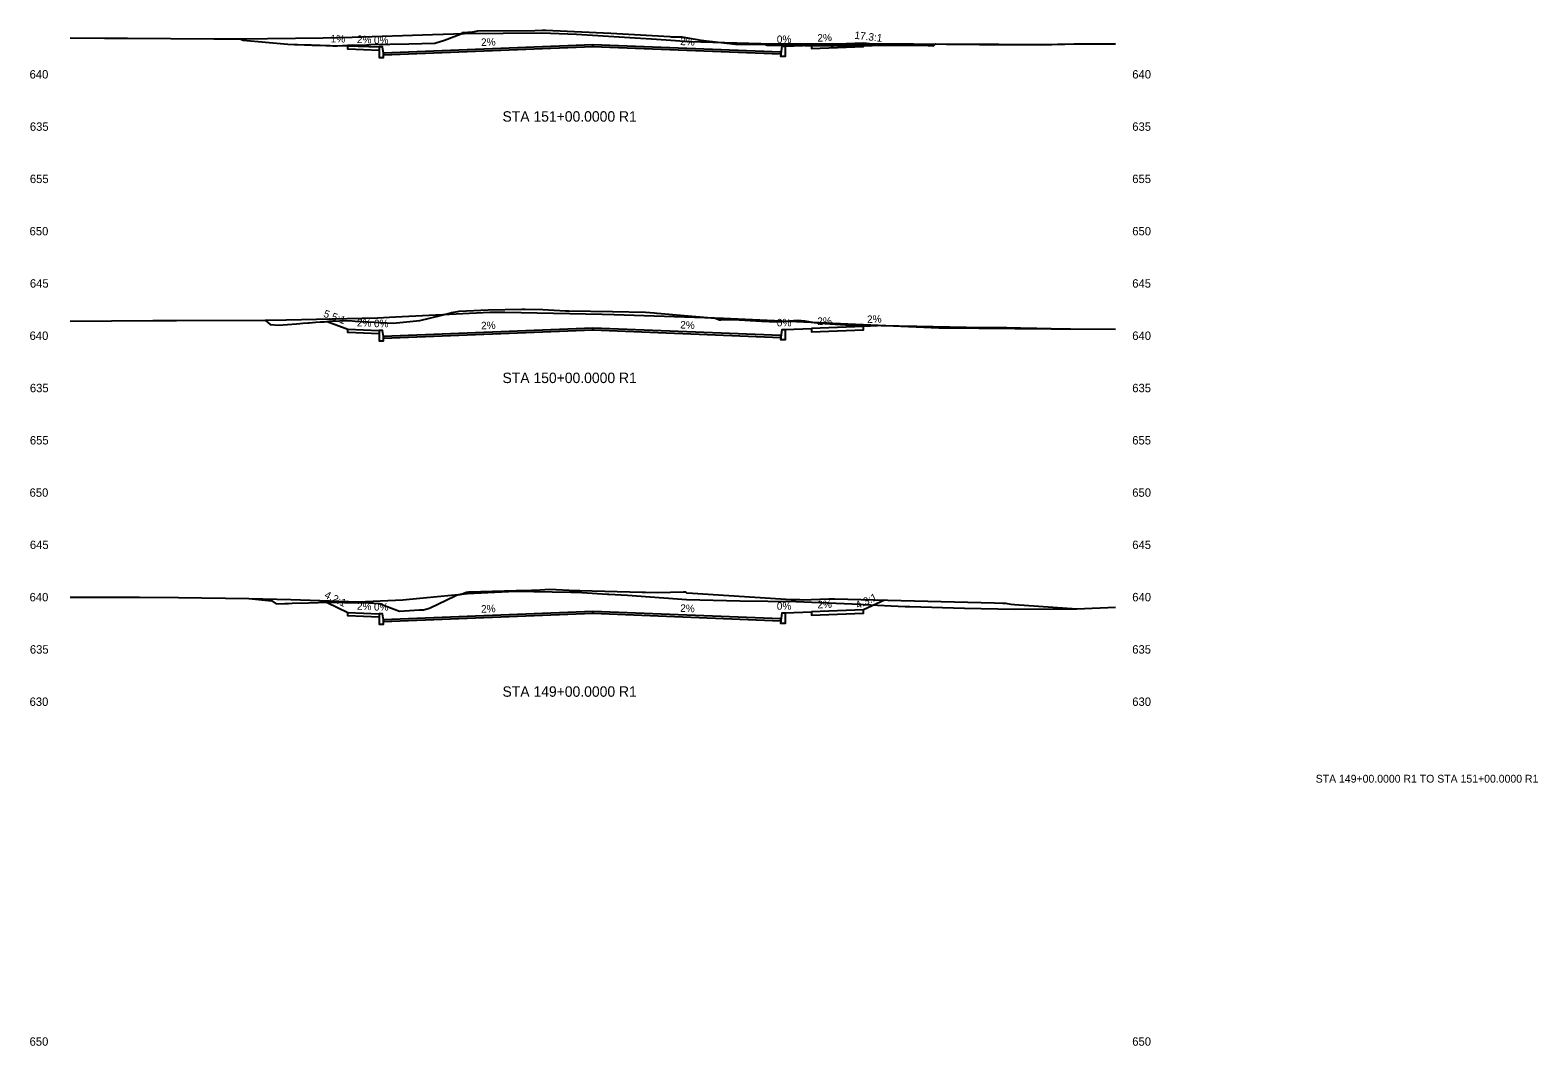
# Model space of a CAD drawing. Extents: x 12 to 301, y 16 to 1707.
# Drawn here: x 12.4 to 300.8, y 1315.6 to 1509.8 of the extents above; entities that cross this region are included whole.
import ezdxf

# ---------------------------------------------------------------- set-up
doc = ezdxf.new("R2010")
doc.units = 0
for name, color, linetype in [('BORD_text_large_2', 7, 'Continuous'), ('Default', 7, 'Continuous'), ('Draft_XS_Point_Label_Indicator', 7, 'Continuous'), ('Draft_XS_Text', 7, 'Continuous'), ('Grade_Veg_Grass', 7, 'Continuous'), ('P_XS_Sections', 7, 'Continuous'), ('Road_Curb', 7, 'Continuous'), ('Road_Pave_Asphalt', 7, 'Continuous'), ('Road_Sidewalk', 7, 'Continuous'), ('Terrain_Exterior', 7, 'Continuous')]:
    doc.layers.add(name, color=color, linetype=linetype)

msp = doc.modelspace()

# ---------------------------------------------------------------- linework, layer by layer
at = {"layer": 'Default'}
for points in [[(20, 1508.36), (26.58, 1508.35), (30.99, 1508.33), (47.51, 1508.2), (52.47, 1508.19), (53.12, 1507.91), (61.69, 1507.17), (62.92, 1507.13), (63.51, 1507.11), (64.83, 1507.06), (65.88, 1507.03), (66.1, 1507.02), (66.32, 1507.01), (67.86, 1506.96), (68.91, 1506.92), (68.98, 1506.92), (69.06, 1506.92), (69.76, 1506.9), (70.29, 1506.88), (70.32, 1506.88), (70.35, 1506.87), (70.76, 1506.86), (70.76, 1506.86), (71.08, 1506.85), (71.1, 1506.85), (71.1, 1506.85), (71.1, 1506.85), (74.09, 1507.07), (75.94, 1506.97), (77.52, 1507.12), (84.85, 1507.21), (89.82, 1507.36), (91.63, 1507.92), (94.8, 1509.15), (95.17, 1509.38), (97.09, 1509.56), (98.03, 1509.72), (108.95, 1509.81), (110.3, 1509.85), (110.54, 1509.85), (110.95, 1509.84), (110.97, 1509.83), (123.47, 1509.25), (131.36, 1508.81), (134.76, 1508.61), (135, 1508.59), (135.63, 1508.59), (136.13, 1508.57), (137.07, 1508.58), (140.67, 1507.92), (147.32, 1507.2), (153.04, 1507.09), (153.21, 1507.02), (153.37, 1506.96), (157.58, 1507.01), (160.52, 1506.94), (165.62, 1506.88), (165.97, 1506.83), (180.94, 1506.98), (182.19, 1507.01), (183.17, 1506.95), (185.21, 1506.86), (185.38, 1507.07), (185.55, 1507.25), (196.01, 1507.19), (197.72, 1507.2), (205.81, 1507.07), (206.09, 1507.08), (207.84, 1507.13), (208.95, 1507.16), (210.34, 1507.19), (212.03, 1507.23), (214.93, 1507.23), (220, 1507.27)], [(20, 1454.16), (35.86, 1454.3), (40.4, 1454.32), (57.35, 1454.41), (58.28, 1453.58), (59.9, 1453.44), (63.34, 1453.69), (63.94, 1453.74), (64.55, 1453.79), (65.56, 1453.86), (65.65, 1453.87), (65.74, 1453.88), (67.04, 1453.97), (67.93, 1454.04), (67.96, 1454.04), (68, 1454.05), (68.63, 1454.09), (69.1, 1454.13), (69.12, 1454.13), (69.14, 1454.13), (69.51, 1454.16), (69.58, 1454.16), (69.63, 1454.17), (69.64, 1454.17), (73.44, 1454.29), (74.56, 1454.21), (80.58, 1453.87), (81.8, 1453.82), (86.9, 1454.3), (90.86, 1455.28), (92.83, 1455.8), (92.96, 1455.86), (94.11, 1456.04), (94.44, 1456.11), (99.97, 1456.37), (106.41, 1456.48), (106.78, 1456.47), (107.1, 1456.47), (110.44, 1456.43), (114.77, 1456.18), (115.05, 1456.17), (115.4, 1456.17), (123.81, 1456.02), (130.1, 1455.92), (131.78, 1455.76), (132.23, 1455.71), (132.28, 1455.72), (132.3, 1455.71), (143.42, 1454.74), (144.24, 1454.46), (144.5, 1454.46), (145.95, 1454.49), (146.94, 1454.52), (152.26, 1454.17), (155.22, 1454.07), (155.98, 1454.14), (159.22, 1454.35), (160.5, 1454.24), (162.35, 1453.92), (163.47, 1453.8), (168.39, 1453.48), (182, 1453.22), (191.45, 1453.05), (199.23, 1452.98), (204.44, 1452.82), (204.98, 1452.82), (205.94, 1452.8), (206.18, 1452.8), (206.19, 1452.8), (207.72, 1452.76), (207.76, 1452.75), (207.82, 1452.75), (211.42, 1452.72), (220, 1452.64)], [(20, 1401.41), (33.28, 1401.39), (40.74, 1401.34), (54.21, 1401.14), (58.58, 1400.69), (59.47, 1400.14), (61.08, 1400.19), (61.81, 1400.21), (62.52, 1400.24), (65.64, 1400.34), (67.47, 1400.4), (67.83, 1400.41), (67.83, 1400.41), (77.11, 1400.34), (79.17, 1400.19), (83.06, 1398.71), (86.85, 1398.98), (87.6, 1398.95), (88.8, 1399.28), (93.69, 1401.65), (93.94, 1401.79), (94.56, 1401.9), (94.68, 1401.96), (95.01, 1402.02), (95.85, 1402.34), (96.31, 1402.41), (105.37, 1402.64), (108.27, 1402.74), (108.43, 1402.74), (108.96, 1402.74), (111.78, 1402.91), (116.69, 1402.7), (116.78, 1402.7), (116.79, 1402.7), (117.35, 1402.7), (117.54, 1402.69), (129.47, 1402.38), (129.5, 1402.37), (130.1, 1402.33), (132.38, 1402.3), (137.39, 1402.43), (137.77, 1402.42), (137.91, 1402.25), (137.92, 1402.24), (139.09, 1402.17), (157.97, 1400.98), (158.8, 1400.93), (159.47, 1400.93), (159.62, 1400.92), (160.08, 1400.89), (165.17, 1401.08), (166.27, 1401.05), (179.04, 1400.77), (196.85, 1400.31), (198.43, 1400.28), (198.44, 1400.28), (198.44, 1400.28), (198.45, 1400.28), (198.47, 1400.27), (198.48, 1400.27), (198.49, 1400.27), (198.5, 1400.27), (198.5, 1400.27), (198.51, 1400.27), (198.53, 1400.27), (198.56, 1400.26), (198.6, 1400.26), (198.65, 1400.25), (198.68, 1400.25), (198.73, 1400.24), (198.82, 1400.23), (198.95, 1400.22), (199.26, 1400.18), (200.02, 1400.08), (200.7, 1399.97), (212.6, 1399.18), (220, 1399.5)]]:
    msp.add_lwpolyline(points, dxfattribs=at)
at = {"layer": 'Grade_Veg_Grass'}
for points in [[(69.17, 1506.92), (69.17, 1506.92), (73.17, 1506.87)], [(156.83, 1506.79), (161.83, 1506.99)], [(175.83, 1506.93), (171.83, 1507.39), (171.83, 1507.39)], [(69.17, 1454.13), (69.17, 1454.13), (73.17, 1452.67)], [(156.83, 1452.59), (161.83, 1452.79)], [(175.83, 1453.34), (171.83, 1453.19), (171.83, 1453.19)], [(69.17, 1400.4), (69.17, 1400.4), (73.17, 1398.47)], [(175.83, 1400.84), (175.83, 1400.84), (171.83, 1398.99)], [(156.83, 1398.39), (161.83, 1398.59)]]:
    msp.add_lwpolyline(points, dxfattribs=at)
at = {"layer": 'Road_Curb'}
for points in [[(79.17, 1506.63), (79.17, 1504.63), (80, 1504.63), (80, 1505.47), (79.77, 1506.63), (79.17, 1506.63)], [(156.83, 1506.79), (156.83, 1504.79), (156, 1504.79), (156.23, 1506.79), (156.83, 1506.79)], [(79.17, 1452.43), (79.17, 1450.43), (80, 1450.43), (80, 1451.27), (79.77, 1452.43), (79.17, 1452.43)], [(156.83, 1452.59), (156.83, 1450.59), (156, 1450.59), (156.23, 1452.59), (156.83, 1452.59)], [(79.17, 1398.23), (79.17, 1396.23), (80, 1396.23), (80, 1397.07), (79.77, 1398.23), (79.17, 1398.23)], [(156.83, 1398.39), (156.83, 1396.39), (156, 1396.39), (156.23, 1398.39), (156.83, 1398.39)]]:
    msp.add_lwpolyline(points, dxfattribs=at)
at = {"layer": 'Road_Pave_Asphalt'}
for points in [[(120, 1507.07), (80, 1505.47), (80, 1505.47), (80, 1505.13), (120, 1506.73), (120, 1506.73), (120, 1507.07), (120, 1507.07), (120, 1507.07)], [(120, 1507.07), (120, 1507.07), (120, 1507.07), (120, 1506.73), (120, 1506.73), (156, 1505.29), (156, 1505.63), (156, 1505.63), (120, 1507.07)], [(120, 1452.87), (80, 1451.27), (80, 1451.27), (80, 1450.93), (120, 1452.53), (120, 1452.53), (120, 1452.87), (120, 1452.87), (120, 1452.87)], [(120, 1452.87), (120, 1452.87), (120, 1452.87), (120, 1452.53), (120, 1452.53), (156, 1451.09), (156, 1451.43), (156, 1451.43), (120, 1452.87)], [(120, 1398.67), (80, 1397.07), (80, 1397.07), (80, 1396.73), (120, 1398.33), (120, 1398.33), (120, 1398.67), (120, 1398.67), (120, 1398.67)], [(120, 1398.67), (120, 1398.67), (120, 1398.67), (120, 1398.33), (120, 1398.33), (156, 1396.89), (156, 1397.23), (156, 1397.23), (120, 1398.67)]]:
    msp.add_lwpolyline(points, dxfattribs=at)
at = {"layer": 'Road_Sidewalk'}
for points in [[(79.17, 1506.63), (79.17, 1505.97), (73.17, 1506.21), (73.17, 1506.87), (79.17, 1506.63)], [(161.83, 1506.99), (161.83, 1506.33), (171.83, 1506.73), (171.83, 1507.39), (161.83, 1506.99)], [(79.17, 1452.43), (79.17, 1451.77), (73.17, 1452.01), (73.17, 1452.67), (79.17, 1452.43)], [(161.83, 1452.79), (161.83, 1452.13), (171.83, 1452.53), (171.83, 1453.19), (161.83, 1452.79)], [(161.83, 1398.59), (161.83, 1397.93), (171.83, 1398.33), (171.83, 1398.99), (161.83, 1398.59)], [(79.17, 1398.23), (79.17, 1397.57), (73.17, 1397.81), (73.17, 1398.47), (79.17, 1398.23)]]:
    msp.add_lwpolyline(points, dxfattribs=at)
at = {"layer": 'Terrain_Exterior'}
for points in [[(20, 1508.36), (26.58, 1508.35), (30.99, 1508.33), (47.51, 1508.2), (52.47, 1508.19), (68.44, 1508.4), (73.96, 1508.52), (89.37, 1509.01), (95.44, 1509.24), (110.29, 1509.32), (116.92, 1509.1), (129.16, 1508.33), (131.22, 1508.2), (134.05, 1508), (135.86, 1507.87), (138.4, 1507.68), (152.15, 1507.27), (159.89, 1507.24), (173.08, 1507.24), (181.37, 1507.23), (194.01, 1507.11), (202.85, 1507.09), (214.93, 1507.21), (220, 1507.26)], [(20, 1454.16), (35.86, 1454.3), (40.4, 1454.32), (57.35, 1454.41), (61.32, 1454.43), (78.83, 1454.85), (82.25, 1455.03), (100.31, 1455.88), (103.18, 1455.91), (121.79, 1455.54), (124.11, 1455.45), (143.28, 1454.82), (145.04, 1454.77), (146.34, 1454.71), (161.76, 1454), (164.76, 1453.86), (165.96, 1453.8), (186.24, 1452.91), (186.89, 1452.89), (207.72, 1452.75), (207.82, 1452.75), (211.42, 1452.72), (220, 1452.64)], [(20, 1401.41), (33.28, 1401.39), (40.74, 1401.34), (54.21, 1401.14), (62.22, 1400.95), (75.14, 1400.48), (83.7, 1400.87), (86.95, 1401.2), (94.95, 1402), (96.07, 1402.11), (105.19, 1402.52), (115.81, 1402.38), (116.99, 1402.36), (122.83, 1402), (123.1, 1401.98), (126.67, 1401.76), (137.92, 1400.96), (148.15, 1400.68), (158.85, 1400.54), (169.63, 1400.1), (171.3, 1400.03), (171.83, 1400), (179.78, 1399.62), (180.64, 1399.6), (191.11, 1399.3), (200.7, 1399.07), (212.6, 1399.18), (220, 1399.5)]]:
    msp.add_lwpolyline(points, dxfattribs=at)

# ---------------------------------------------------------------- texts
at = {"layer": 'BORD_text_large_2'}
msp.add_text('STA 149+00.0000 R1 TO STA 151+00.0000 R1', height=1.5, dxfattribs=at).set_placement((258.32, 1365.92))
at = {"layer": 'Draft_XS_Point_Label_Indicator'}
for p in [(69.16, 1506.9), (73.16, 1506.86), (79.16, 1506.62), (79.76, 1506.62), (119.99, 1507.06), (119.99, 1507.06), (156.22, 1506.78), (156.82, 1506.78), (161.82, 1506.98), (171.82, 1507.38), (175.82, 1506.92), (79.99, 1505.46), (155.99, 1505.62), (69.16, 1454.12), (73.16, 1452.66), (79.16, 1452.42), (79.76, 1452.42), (79.99, 1451.26), (119.99, 1452.86), (119.99, 1452.86), (155.99, 1451.42), (156.22, 1452.58), (156.82, 1452.58), (161.82, 1452.78), (171.82, 1453.18), (175.82, 1453.33), (69.16, 1400.39), (171.82, 1398.98), (175.82, 1400.83), (73.16, 1398.46), (79.16, 1398.22), (79.76, 1398.22), (79.99, 1397.06), (119.99, 1398.66), (119.99, 1398.66), (155.99, 1397.22), (156.22, 1398.38), (156.82, 1398.38), (161.82, 1398.58)]:
    msp.add_text('X', height=0.024, dxfattribs=at).set_placement(p)
at = {"layer": 'Draft_XS_Text'}
for s, rotation, p in [('1%', 359.4187, (69.86, 1507.51)), ('1%', 359.4187, (69.86, 1507.51)), ('1%', 359.4187, (69.86, 1507.51)), ('2%', 357.7094, (74.88, 1507.41)), ('2%', 357.7094, (74.88, 1507.41)), ('2%', 357.7094, (74.88, 1507.41)), ('0%', 360, (78.15, 1507.23)), ('0%', 360, (78.15, 1507.23)), ('0%', 360, (78.15, 1507.23)), ('0%', 0, (155.22, 1507.39)), ('0%', 0, (155.22, 1507.39)), ('0%', 0, (155.22, 1507.39)), ('2%', 2.2906, (163, 1507.64)), ('2%', 2.2906, (163, 1507.64)), ('2%', 2.2906, (163, 1507.64)), ('17.3:1', 353.4149, (170.01, 1508.21)), ('17.3:1', 353.4149, (170.01, 1508.21)), ('17.3:1', 353.4149, (170.01, 1508.21)), ('2%', 2.2906, (98.66, 1506.81)), ('2%', 2.2906, (98.66, 1506.81)), ('2%', 2.2906, (98.66, 1506.81)), ('2%', 357.7094, (136.71, 1507)), ('2%', 357.7094, (136.71, 1507)), ('2%', 357.7094, (136.71, 1507)), ('5.5:1', 339.962, (68.37, 1455.06)), ('5.5:1', 339.962, (68.37, 1455.06)), ('5.5:1', 339.962, (68.37, 1455.06)), ('2%', 357.7094, (74.88, 1453.21)), ('2%', 357.7094, (74.88, 1453.21)), ('2%', 357.7094, (74.88, 1453.21)), ('0%', 0, (78.15, 1453.03)), ('0%', 0, (78.15, 1453.03)), ('0%', 0, (78.15, 1453.03)), ('2%', 2.2906, (98.66, 1452.61)), ('2%', 2.2906, (98.66, 1452.61)), ('2%', 2.2906, (98.66, 1452.61)), ('2%', 357.7094, (136.71, 1452.8)), ('2%', 357.7094, (136.71, 1452.8)), ('2%', 357.7094, (136.71, 1452.8)), ('0%', 0, (155.22, 1453.19)), ('0%', 0, (155.22, 1453.19)), ('0%', 0, (155.22, 1453.19)), ('2%', 2.2906, (163, 1453.44)), ('2%', 2.2906, (163, 1453.44)), ('2%', 2.2906, (163, 1453.44)), ('2%', 2.0751, (172.5, 1453.82)), ('2%', 2.0751, (172.5, 1453.82)), ('2%', 2.0751, (172.5, 1453.82)), ('4.2:1', 334.3023, (68.54, 1401.36)), ('4.2:1', 334.3023, (68.54, 1401.36)), ('4.2:1', 334.3023, (68.54, 1401.36)), ('4.3:1', 24.7976, (170.68, 1399.12)), ('4.3:1', 24.7976, (170.68, 1399.12)), ('4.3:1', 24.7976, (170.68, 1399.12)), ('2%', 357.7094, (74.88, 1399.01)), ('2%', 357.7094, (74.88, 1399.01)), ('2%', 357.7094, (74.88, 1399.01)), ('0%', 360, (78.15, 1398.83)), ('0%', 360, (78.15, 1398.83)), ('0%', 360, (78.15, 1398.83)), ('2%', 2.2906, (98.66, 1398.41)), ('2%', 2.2906, (98.66, 1398.41)), ('2%', 2.2906, (98.66, 1398.41)), ('2%', 357.7094, (136.71, 1398.6)), ('2%', 357.7094, (136.71, 1398.6)), ('2%', 357.7094, (136.71, 1398.6)), ('0%', 360, (155.22, 1398.99)), ('0%', 360, (155.22, 1398.99)), ('0%', 360, (155.22, 1398.99)), ('2%', 2.2906, (163, 1399.24)), ('2%', 2.2906, (163, 1399.24)), ('2%', 2.2906, (163, 1399.24))]:
    msp.add_text(s, height=1.44, rotation=rotation, dxfattribs=at).set_placement(p)
for s, height, p in [('640', 1.608, (12.26, 1500.6)), ('640', 1.608, (223.22, 1500.6)), ('STA 151+00.0000 R1', 1.992, (102.74, 1492.35)), ('635', 1.608, (12.32, 1490.6)), ('635', 1.608, (223.22, 1490.6)), ('655', 1.608, (12.32, 1480.6)), ('655', 1.608, (223.22, 1480.6)), ('650', 1.608, (12.26, 1470.6)), ('650', 1.608, (223.22, 1470.6)), ('645', 1.608, (12.32, 1460.6)), ('645', 1.608, (223.22, 1460.6)), ('640', 1.608, (12.26, 1450.6)), ('640', 1.608, (223.22, 1450.6)), ('635', 1.608, (12.32, 1440.6)), ('STA 150+00.0000 R1', 1.992, (102.74, 1442.35)), ('635', 1.608, (223.22, 1440.6)), ('655', 1.608, (12.32, 1430.6)), ('655', 1.608, (223.22, 1430.6)), ('650', 1.608, (12.26, 1420.6)), ('650', 1.608, (223.22, 1420.6)), ('645', 1.608, (12.32, 1410.6)), ('645', 1.608, (223.22, 1410.6)), ('640', 1.608, (12.26, 1400.6)), ('640', 1.608, (223.22, 1400.6)), ('635', 1.608, (12.32, 1390.6)), ('635', 1.608, (223.22, 1390.6)), ('630', 1.608, (12.26, 1380.6)), ('STA 149+00.0000 R1', 1.992, (102.74, 1382.35)), ('630', 1.608, (223.22, 1380.6)), ('650', 1.608, (12.26, 1315.6)), ('650', 1.608, (223.22, 1315.6))]:
    msp.add_text(s, height=height, dxfattribs=at).set_placement(p)
at = {"layer": 'P_XS_Sections'}
for p in [(20, 1490), (20, 1440), (20, 1380)]:
    msp.add_text('-', height=0.0001, dxfattribs=at).set_placement(p)

doc.saveas('drawing.dxf')
